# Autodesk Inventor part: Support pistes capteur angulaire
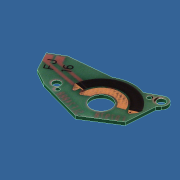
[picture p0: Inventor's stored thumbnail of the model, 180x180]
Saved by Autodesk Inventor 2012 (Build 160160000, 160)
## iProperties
Created: 2011-10
Part Number: Support pistes capteur angulaire
Document SubType Name: Modeling
Designer: Laur
Density: 1.38 g/cm^3
Material: Phénolique
Mass: 0.273708 g
Surface Area: 5.80607 cm^2
Volume: 0.198339 cm^3
Author: Laur
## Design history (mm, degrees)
sketch "Esquisse1"
  geometry: L1 (0.778, 16.859)-(29.221, 16.848); L2 (29.221, 16.848)-(29.214, 0.201); L3 (29.214, 0.201)-(0.771, 0.212); L4 (0.771, 0.212)-(0.778, 16.859); L5 (4.832, 12.902)-(1.158, 10.769); L6 (1.158, 10.769)-(3.898, 5.676); L7 (3.898, 5.676)-(7.958, 3.405); L8 (7.958, 3.405)-(19.495, 0.204); L9 (19.495, 0.204)-(27.58, 5.328); L10 (27.58, 5.328)-(28.116, 12.877); L11 (4.832, 12.902)-(15.629, 13.919); L12 (23.157, 14.511)-(26.7, 16.404); L13 (9.603, 5.142)-(27.685, 14.8); L14 (0, -3.458)-(0, 20.746) reference; L15 (-5.987, 0)-(35.921, 0) reference; L16 (28.116, 12.877)-(28.854, 13.774); C1 r 2.65 at (20, 6.5); C2 r 1 at (27.685, 14.8); C3 r 0.5 at (25.2, 14.1); C4 r 1 at (9.603, 5.142); C5 r 0.5 at (11.1, 3.9); A1 r 8.611 centre (20, 6.5) between (23.157, 14.511) and (15.629, 13.919); A2 r 1.733 centre (27.517, 14.876) between (28.854, 13.774) and (26.7, 16.404); 1 further point; 1 other entity
  constraints: 20 end point, 7 centre point, 4 point on circle, 2 coincident, 2 tangent, 1 parallel, 1 point on line, 3 other
  dimensions: "d9" = 5.3 diameter of C1; "d30" = 1 diameter of C3; "d31" = 2 diameter of C2; "d32" = 2 diameter of C4; "d33" = 1 diameter of C5; "d37" = 8.9 horizontal distance of C1.centre C5.centre; "d39" = 2.6 vertical distance of C5.centre C1.centre; "d40" = 7.6 vertical distance of C3.centre A1.centre; "d42" = 5.2 horizontal distance of C1.centre C3.centre; "d81" = 8.3 vertical distance of A1.centre C2.centre; "d189" = 10.485 distance of L13.start C1.centre; "d192" = 20.5 distance of C2.centre L13.start; "d249" = 3.7 distance from line of C1.centre L13; "d264" = 20 horizontal distance of point (0, 0) C1.centre; "d265" = 6.50048 vertical distance of point (0, 0) C1.centre; "d335" = 0.022187 deg angle of L3 L15 (derived); "d337" = 0.8 distance of L3.end point (0, 0)
  node "Image3"
extrude "Extrusion1" new body sketch "Esquisse1" distance "d99" = 0.8; taper "d100" = 0 deg
feature "Décalcomanie1"
sketch "Esquisse2"
  geometry: L1 (3.115, -7.489)-(-35.416, -5.384); L2 (-35.416, -5.384)-(-33.837, 23.514); L3 (-33.837, 23.514)-(4.693, 21.409); L4 (4.693, 21.409)-(3.115, -7.489); 1 other entity
  constraints: 2 other
feature "Décalcomanie2" sketch "Esquisse2"
node "Solide1"
node "Corps solides"
node "Corps surfaciques"
node "Image6"
other parameters: "d29" = 17
